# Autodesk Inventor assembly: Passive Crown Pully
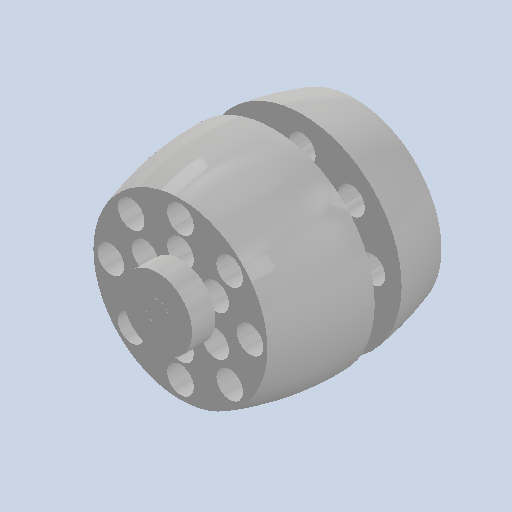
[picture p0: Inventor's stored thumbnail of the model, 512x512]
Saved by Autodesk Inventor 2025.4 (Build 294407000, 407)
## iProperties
Created: 2026-09
Part Number: Passive Crown Pully
Document SubType Name: Assembly
Designer: AdminForWorker
Title: Passive Crown Pully v9
Author: AdminForWorker
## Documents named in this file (5)
- c:\worker\convert-fusion-r05-cosv3\tmp\job-1\95\temp\files\d128062f-b306-4666-833c-9495a6440927\388c706d-a01d-4e5f-9779-3ff9cea6de5c.iam
- c:\worker\convert-fusion-r05-cosv3\tmp\job-1\95\temp\files\d128062f-b306-4666-833c-9495a6440927\Bearing 4_12 ID_OD v1.ipt
- c:\worker\convert-fusion-r05-cosv3\tmp\job-1\95\temp\files\d128062f-b306-4666-833c-9495a6440927\32x4 mm Dowel v1.ipt
- c:\worker\convert-fusion-r05-cosv3\tmp\job-1\95\temp\files\d128062f-b306-4666-833c-9495a6440927\bottom.ipt
- c:\worker\convert-fusion-r05-cosv3\tmp\job-1\95\temp\files\d128062f-b306-4666-833c-9495a6440927\top.ipt
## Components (5 placed, 4 different names)
1. Bearing 4/12 ID/OD v1:1
2. 32x4 mm Dowel v1:1
3. Bearing 4/12 ID/OD v1:2
4. bottom:1
5. top:1
